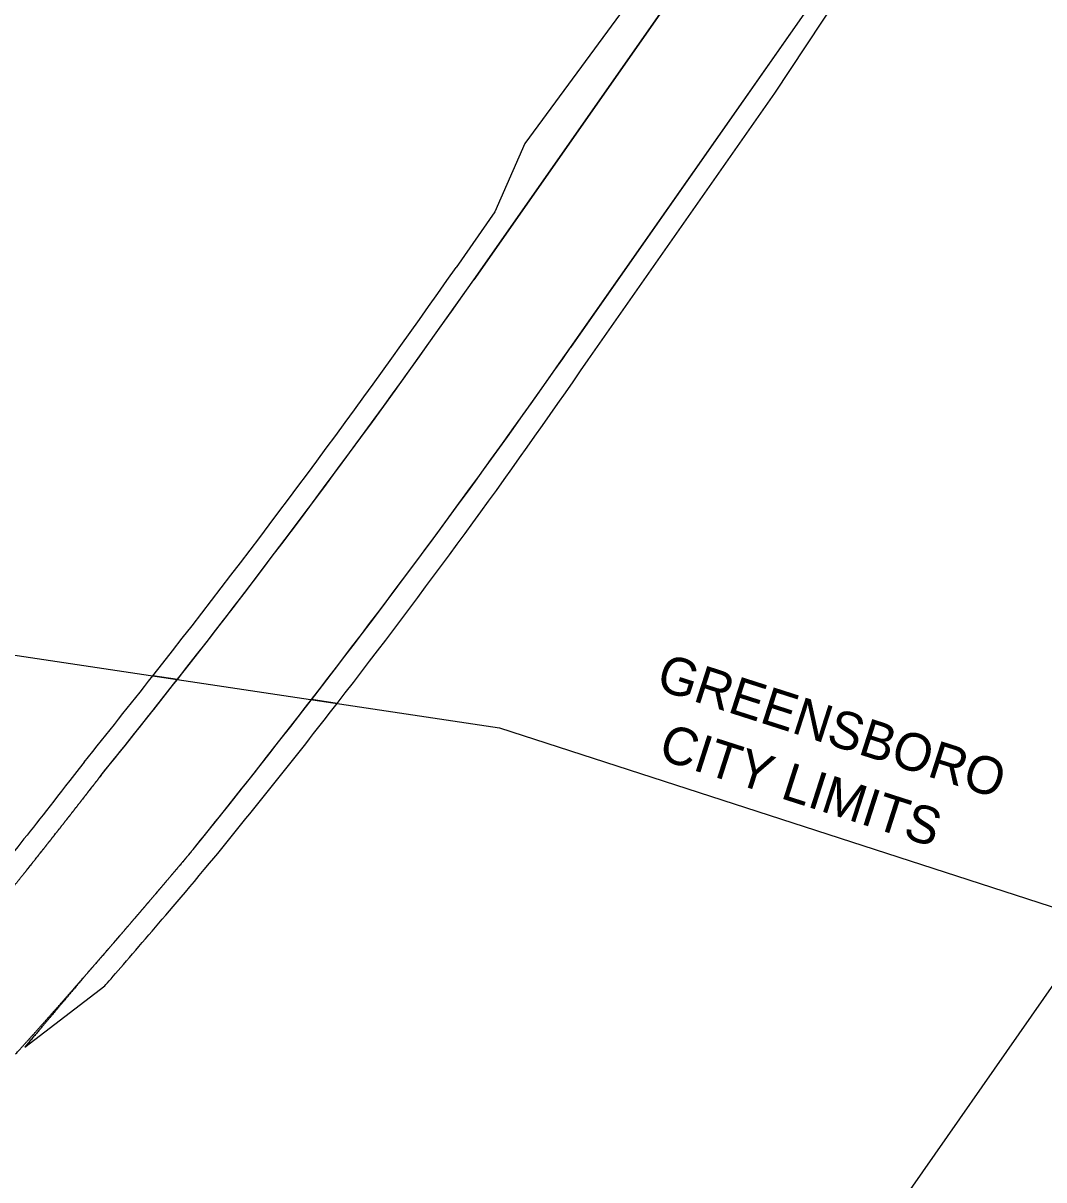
# Model space of a CAD drawing. Extents: x 1731327 to 1735374, y 884856 to 889832.
# Drawn here: x 1732032.5 to 1732222.4, y 885272.3 to 885487.7 of the extents above; entities that cross this region are included whole.
import ezdxf

# ---------------------------------------------------------------- set-up
doc = ezdxf.new("R2010")
doc.units = 0
for name, color, linetype in [('Exist Horizontal Baseline Alignment', 7, 'Continuous'), ('Exist Other Culture Area Outline', 7, 'Continuous'), ('Exist Other Culture Sign Text', 7, 'Continuous'), ('Exist Structure Minor Pipes RCP 24 Inch', 7, 'Continuous')]:
    doc.layers.add(name, color=color, linetype=linetype)

msp = doc.modelspace()

# ---------------------------------------------------------------- linework, layer by layer
at = {"layer": 'Exist Other Culture Area Outline'}
msp.add_lwpolyline([(1732238.91, 886072.74), (1731769.46, 885400.02), (1732118.14, 885156.7), (1732587.59, 885829.41)], close=True, dxfattribs=at)
at = {"layer": 'Exist Other Culture Sign Text'}
msp.add_lwpolyline([(1731775.28, 885408.36), (1732121.12, 885356.5), (1732232.4, 885320.42)], dxfattribs=at)
at = {"layer": 'Exist Structure Minor Pipes RCP 24 Inch'}
for p, q in [((1732169.62, 885516.04), (1732116.34, 885439.87)), ((1732116.34, 885439.87), (1732169.62, 885516.04)), ((1732134.37, 885427.26), (1732191.03, 885508.26)), ((1732190.43, 885507.41), (1732134.37, 885427.26)), ((1732172.39, 885474.63), (1732193.35, 885506.34)), ((1732137.65, 885424.97), (1732172.39, 885474.63)), ((1732125.88, 885465.23), (1732120.29, 885452.5)), ((1732120.29, 885452.5), (1732113.06, 885442.17)), ((1732061.21, 885365.48), (1732056.66, 885366.17)), ((1732056.66, 885366.17), (1732061.21, 885365.48)), ((1732086.17, 885361.74), (1732090.93, 885361.03)), ((1732090.93, 885361.03), (1732086.17, 885361.74)), ((1732032.82, 885297.07), (1732047.69, 885308.44))]:
    msp.add_line(p, q, dxfattribs=at)
msp.add_lwpolyline([(1732160.1, 885512.01), (1732152.44, 885501.5), (1732125.88, 885465.23)], dxfattribs=at)
for centre, radius, start, end in [((1730732.36, 886408.03), 1685, 321.80683, 325.02552), ((1730732.37, 886408.04), 1689, 321.1108, 325.02513), ((1730732.37, 886408.04), 1689, 321.88369, 325.02513), ((1730732.37, 886408.04), 1711, 321.1108, 325.02513), ((1730732.37, 886408.04), 1711, 322.30115, 325.02513), ((1730992.09, 886212.81), 1390.32, 322.21856, 325.48235), ((1730732.36, 886408.03), 1685, 321.10848, 321.80683), ((1730732.37, 886408.04), 1689, 321.1108, 321.88369), ((1730732.37, 886408.04), 1711, 321.1108, 322.30115), ((1730992.09, 886212.81), 1390.32, 320.65011, 322.21856)]:
    msp.add_arc(centre, radius, start, end, dxfattribs=at)
for points, degree in [([(1732043.86, 885350.1), (1732038.81, 885343.58), (1732032.68, 885335.78), (1732026.49, 885328.04), (1732025.45, 885326.74)], 3), ([(1732047.02, 885347.65), (1732046.89, 885347.48), (1732046.75, 885347.3), (1732046.61, 885347.12), (1732046.47, 885346.95), (1732046.34, 885346.77), (1732046.2, 885346.59), (1732046.06, 885346.42), (1732045.93, 885346.24), (1732045.79, 885346.06), (1732045.65, 885345.89), (1732045.51, 885345.71), (1732045.38, 885345.53), (1732045.24, 885345.35), (1732045.1, 885345.18), (1732044.97, 885345), (1732044.83, 885344.82), (1732044.69, 885344.65), (1732044.55, 885344.47), (1732044.42, 885344.29), (1732044.28, 885344.12), (1732044.14, 885343.94), (1732044, 885343.76), (1732043.87, 885343.59), (1732043.73, 885343.41), (1732043.59, 885343.23), (1732043.45, 885343.06), (1732043.32, 885342.88), (1732043.18, 885342.71), (1732043.04, 885342.53), (1732042.9, 885342.35), (1732042.76, 885342.18), (1732042.63, 885342), (1732042.49, 885341.82), (1732042.35, 885341.65), (1732042.21, 885341.47), (1732042.08, 885341.29), (1732041.94, 885341.12), (1732041.8, 885340.94), (1732041.66, 885340.76), (1732041.52, 885340.59), (1732041.39, 885340.41), (1732041.25, 885340.24), (1732041.11, 885340.06), (1732040.97, 885339.88), (1732040.83, 885339.71), (1732040.7, 885339.53), (1732040.56, 885339.35), (1732040.42, 885339.18), (1732040.28, 885339), (1732040.14, 885338.83), (1732040.01, 885338.65), (1732039.87, 885338.47), (1732039.73, 885338.3), (1732039.59, 885338.12), (1732039.45, 885337.95), (1732039.31, 885337.77), (1732039.18, 885337.59), (1732039.04, 885337.42), (1732038.9, 885337.24), (1732038.76, 885337.07), (1732038.62, 885336.89), (1732038.48, 885336.71), (1732038.35, 885336.54), (1732038.21, 885336.36), (1732038.07, 885336.19), (1732037.93, 885336.01), (1732037.79, 885335.84), (1732037.65, 885335.66), (1732037.51, 885335.48), (1732037.38, 885335.31), (1732037.24, 885335.13), (1732037.1, 885334.96), (1732037.01, 885334.85), (1732036.92, 885334.74), (1732036.84, 885334.63)], 3), ([(1732045.02, 885345.07), (1732045.14, 885345.23), (1732045.26, 885345.38), (1732045.38, 885345.53), (1732045.51, 885345.71), (1732045.65, 885345.89), (1732045.79, 885346.06), (1732045.93, 885346.24), (1732046.06, 885346.42), (1732046.2, 885346.59), (1732046.34, 885346.77), (1732046.47, 885346.95), (1732046.61, 885347.12), (1732046.75, 885347.3), (1732046.89, 885347.48), (1732047.02, 885347.65)], 3), ([(1732043.51, 885343.14), (1732043.58, 885343.23), (1732043.66, 885343.32), (1732043.73, 885343.41), (1732043.87, 885343.59), (1732044, 885343.76), (1732044.14, 885343.94), (1732044.28, 885344.12), (1732044.42, 885344.29), (1732044.55, 885344.47), (1732044.55, 885344.47), (1732044.55, 885344.47), (1732044.55, 885344.47)], 3), ([(1732044.55, 885344.47), (1732044.69, 885344.65), (1732044.83, 885344.82), (1732044.97, 885345), (1732044.98, 885345.02), (1732045, 885345.05), (1732045.02, 885345.07)], 3), ([(1732044.55, 885344.47), (1732044.55, 885344.47), (1732044.55, 885344.47), (1732044.55, 885344.47)], 2), ([(1732041.66, 885340.76), (1732041.66, 885340.76), (1732041.66, 885340.76), (1732041.66, 885340.76), (1732041.8, 885340.94), (1732041.94, 885341.12), (1732042.08, 885341.29), (1732042.21, 885341.47), (1732042.35, 885341.65), (1732042.49, 885341.82), (1732042.56, 885341.91), (1732042.62, 885342), (1732042.69, 885342.08)], 3), ([(1732042.69, 885342.08), (1732042.76, 885342.17), (1732042.83, 885342.26), (1732042.9, 885342.35), (1732042.95, 885342.41), (1732042.99, 885342.46), (1732043.03, 885342.52)], 3), ([(1732043.03, 885342.52), (1732043.13, 885342.64), (1732043.22, 885342.76), (1732043.32, 885342.88), (1732043.38, 885342.97), (1732043.45, 885343.05), (1732043.51, 885343.14)], 3), ([(1732038.43, 885336.65), (1732038.54, 885336.79), (1732038.65, 885336.93), (1732038.76, 885337.07), (1732038.9, 885337.24), (1732039.04, 885337.42), (1732039.18, 885337.59), (1732039.31, 885337.77), (1732039.45, 885337.95), (1732039.59, 885338.12), (1732039.73, 885338.3), (1732039.87, 885338.47), (1732040.01, 885338.65), (1732040.14, 885338.83), (1732040.28, 885339), (1732040.42, 885339.18), (1732040.47, 885339.24), (1732040.51, 885339.29), (1732040.56, 885339.35)], 3), ([(1732040.56, 885339.35), (1732040.65, 885339.47), (1732040.74, 885339.59), (1732040.83, 885339.71), (1732040.97, 885339.88), (1732041.11, 885340.06), (1732041.25, 885340.24), (1732041.39, 885340.41), (1732041.52, 885340.59), (1732041.66, 885340.76)], 3), ([(1732036.84, 885334.63), (1732036.92, 885334.74), (1732037.01, 885334.85), (1732037.1, 885334.96), (1732037.24, 885335.13), (1732037.38, 885335.31), (1732037.51, 885335.48), (1732037.65, 885335.66), (1732037.79, 885335.84), (1732037.93, 885336.01), (1732038.07, 885336.19), (1732038.21, 885336.36), (1732038.35, 885336.54), (1732038.37, 885336.57), (1732038.4, 885336.61), (1732038.43, 885336.65)], 3), ([(1732036.84, 885334.63), (1732036.79, 885334.56), (1732036.73, 885334.49), (1732036.68, 885334.43), (1732036.54, 885334.25), (1732036.4, 885334.08), (1732036.27, 885333.9), (1732036.13, 885333.73), (1732035.99, 885333.55), (1732035.85, 885333.38), (1732035.71, 885333.2), (1732035.57, 885333.02), (1732035.43, 885332.85), (1732035.29, 885332.67), (1732035.15, 885332.5), (1732035.02, 885332.32), (1732034.88, 885332.15), (1732034.74, 885331.97), (1732034.6, 885331.8), (1732034.46, 885331.62), (1732034.32, 885331.45), (1732034.18, 885331.27), (1732034.04, 885331.09), (1732033.9, 885330.92), (1732033.76, 885330.74), (1732033.62, 885330.57), (1732033.48, 885330.39), (1732033.35, 885330.22), (1732033.21, 885330.04), (1732033.07, 885329.87), (1732032.93, 885329.69), (1732032.79, 885329.52), (1732032.65, 885329.34), (1732032.51, 885329.17), (1732032.37, 885328.99), (1732032.23, 885328.82), (1732032.09, 885328.64), (1732031.95, 885328.47), (1732031.81, 885328.29), (1732031.67, 885328.12), (1732031.53, 885327.94), (1732031.39, 885327.77), (1732031.25, 885327.59), (1732031.11, 885327.42), (1732030.97, 885327.24), (1732030.83, 885327.07), (1732030.69, 885326.89), (1732030.55, 885326.72), (1732030.41, 885326.54), (1732030.27, 885326.37), (1732030.13, 885326.19), (1732029.99, 885326.02), (1732029.85, 885325.84), (1732029.71, 885325.67), (1732029.57, 885325.49), (1732029.43, 885325.32), (1732029.29, 885325.14), (1732029.15, 885324.97), (1732029.01, 885324.79), (1732028.87, 885324.62), (1732028.73, 885324.45), (1732028.59, 885324.27), (1732028.45, 885324.1), (1732028.31, 885323.92), (1732028.17, 885323.75), (1732028.03, 885323.57), (1732027.89, 885323.4), (1732027.75, 885323.22), (1732027.61, 885323.05), (1732027.47, 885322.87), (1732027.33, 885322.7), (1732027.19, 885322.53), (1732027.05, 885322.35), (1732026.91, 885322.18), (1732026.77, 885322), (1732026.63, 885321.83), (1732026.6, 885321.78), (1732026.56, 885321.74), (1732026.53, 885321.7)], 3), ([(1732035.12, 885332.45), (1732035.22, 885332.58), (1732035.33, 885332.72), (1732035.43, 885332.85), (1732035.57, 885333.02), (1732035.71, 885333.2), (1732035.85, 885333.38)], 3), ([(1732035.85, 885333.38), (1732035.85, 885333.38), (1732035.85, 885333.38), (1732035.85, 885333.38), (1732035.99, 885333.55), (1732036.13, 885333.73), (1732036.27, 885333.9), (1732036.4, 885334.08), (1732036.54, 885334.25), (1732036.68, 885334.43), (1732036.73, 885334.49), (1732036.79, 885334.56), (1732036.84, 885334.63)], 3), ([(1732053.28, 885321.03), (1732053.38, 885321.15), (1732053.48, 885321.27), (1732053.59, 885321.39), (1732053.74, 885321.57), (1732053.88, 885321.74), (1732054.03, 885321.91), (1732054.18, 885322.08), (1732054.33, 885322.25), (1732054.47, 885322.43), (1732054.62, 885322.6), (1732054.77, 885322.77), (1732054.91, 885322.94), (1732055.06, 885323.12), (1732055.21, 885323.29), (1732055.36, 885323.46), (1732055.5, 885323.63), (1732055.65, 885323.81), (1732055.8, 885323.98), (1732055.95, 885324.15), (1732056.09, 885324.32), (1732056.24, 885324.5), (1732056.39, 885324.67), (1732056.53, 885324.84), (1732056.68, 885325.01), (1732056.83, 885325.19), (1732056.97, 885325.36), (1732057.12, 885325.53), (1732057.27, 885325.7), (1732057.41, 885325.88), (1732057.56, 885326.05), (1732057.71, 885326.22), (1732057.86, 885326.4), (1732058, 885326.57), (1732058.15, 885326.74), (1732058.3, 885326.91), (1732058.44, 885327.09), (1732058.59, 885327.26), (1732058.74, 885327.43), (1732058.88, 885327.61), (1732059.03, 885327.78), (1732059.18, 885327.95), (1732059.32, 885328.12), (1732059.47, 885328.3), (1732059.62, 885328.47), (1732059.76, 885328.64), (1732059.91, 885328.82), (1732060.05, 885328.99), (1732060.2, 885329.16), (1732060.35, 885329.34), (1732060.49, 885329.51), (1732060.64, 885329.68), (1732060.79, 885329.85), (1732060.93, 885330.03), (1732061.08, 885330.2), (1732061.23, 885330.37), (1732061.37, 885330.55), (1732061.52, 885330.72), (1732061.66, 885330.89), (1732061.81, 885331.07), (1732061.96, 885331.24), (1732062.1, 885331.41), (1732062.25, 885331.59), (1732062.39, 885331.76), (1732062.54, 885331.93), (1732062.69, 885332.11), (1732062.83, 885332.28), (1732062.98, 885332.45), (1732063.13, 885332.63), (1732063.27, 885332.8), (1732063.42, 885332.97), (1732063.56, 885333.15), (1732063.71, 885333.32), (1732063.85, 885333.5), (1732064, 885333.67), (1732064.15, 885333.84)], 3), ([(1732063.29, 885332.82), (1732063.28, 885332.82), (1732063.28, 885332.81), (1732063.27, 885332.8), (1732063.13, 885332.63), (1732062.98, 885332.45), (1732062.83, 885332.28), (1732062.83, 885332.28), (1732062.83, 885332.28), (1732062.83, 885332.28)], 3), ([(1732063.43, 885332.99), (1732063.38, 885332.93), (1732063.34, 885332.88), (1732063.29, 885332.82)], 2), ([(1732063.68, 885333.29), (1732063.6, 885333.19), (1732063.51, 885333.09), (1732063.43, 885332.99)], 2), ([(1732064.15, 885333.84), (1732064, 885333.67), (1732063.85, 885333.5), (1732063.71, 885333.32), (1732063.7, 885333.31), (1732063.69, 885333.3), (1732063.68, 885333.29)], 3), ([(1732032.51, 885329.17), (1732032.65, 885329.34), (1732032.79, 885329.52), (1732032.93, 885329.69), (1732033.07, 885329.87), (1732033.21, 885330.04), (1732033.35, 885330.22), (1732033.48, 885330.39), (1732033.62, 885330.57), (1732033.76, 885330.74)], 3), ([(1732033.76, 885330.74), (1732033.79, 885330.77), (1732033.81, 885330.81), (1732033.84, 885330.84)], 2), ([(1732033.76, 885330.74), (1732033.76, 885330.74), (1732033.76, 885330.74), (1732033.76, 885330.74), (1732033.76, 885330.74), (1732033.76, 885330.74), (1732033.76, 885330.74)], 3), ([(1732033.76, 885330.74), (1732033.76, 885330.74), (1732033.76, 885330.74), (1732033.76, 885330.74)], 2), ([(1732033.84, 885330.84), (1732033.95, 885330.98), (1732034.07, 885331.13), (1732034.18, 885331.27), (1732034.32, 885331.45), (1732034.46, 885331.62), (1732034.6, 885331.8), (1732034.71, 885331.94), (1732034.83, 885332.09), (1732034.95, 885332.24)], 3), ([(1732034.95, 885332.24), (1732034.97, 885332.26), (1732034.99, 885332.29), (1732035.02, 885332.32), (1732035.05, 885332.37), (1732035.08, 885332.41), (1732035.12, 885332.45)], 3), ([(1732047.69, 885308.44), (1732048.74, 885309.64), (1732055.3, 885317.2), (1732061.79, 885324.82), (1732067.21, 885331.27)], 3), ([(1732061.82, 885331.08), (1732061.72, 885330.96), (1732061.62, 885330.84), (1732061.52, 885330.72), (1732061.37, 885330.55), (1732061.23, 885330.37), (1732061.08, 885330.2), (1732060.93, 885330.03), (1732060.79, 885329.85), (1732060.64, 885329.68), (1732060.49, 885329.51), (1732060.35, 885329.34), (1732060.2, 885329.16), (1732060.05, 885328.99), (1732059.91, 885328.82), (1732059.76, 885328.64), (1732059.62, 885328.47), (1732059.47, 885328.3), (1732059.32, 885328.12), (1732059.32, 885328.12), (1732059.32, 885328.12), (1732059.32, 885328.12)], 3), ([(1732062.39, 885331.76), (1732062.25, 885331.59), (1732062.1, 885331.41), (1732061.96, 885331.24), (1732061.91, 885331.19), (1732061.87, 885331.13), (1732061.82, 885331.08)], 3), ([(1732062.83, 885332.28), (1732062.69, 885332.11), (1732062.54, 885331.93), (1732062.39, 885331.76)], 2), ([(1732062.83, 885332.28), (1732062.83, 885332.28), (1732062.83, 885332.28), (1732062.83, 885332.28)], 2), ([(1732058.44, 885327.09), (1732058.3, 885326.91), (1732058.15, 885326.74), (1732058, 885326.57), (1732057.86, 885326.4), (1732057.71, 885326.22), (1732057.56, 885326.05), (1732057.41, 885325.88), (1732057.27, 885325.7), (1732057.12, 885325.53)], 3), ([(1732059.32, 885328.12), (1732059.17, 885327.95), (1732059.03, 885327.78), (1732058.88, 885327.61), (1732058.74, 885327.43), (1732058.59, 885327.26), (1732058.44, 885327.09), (1732058.44, 885327.09), (1732058.44, 885327.09), (1732058.44, 885327.09)], 3), ([(1732057.12, 885325.53), (1732056.97, 885325.36), (1732056.83, 885325.19), (1732056.68, 885325.01), (1732056.53, 885324.84), (1732056.39, 885324.67), (1732056.24, 885324.5), (1732056.09, 885324.32), (1732055.95, 885324.15), (1732055.8, 885323.98), (1732055.72, 885323.88), (1732055.63, 885323.79), (1732055.55, 885323.69)], 3), ([(1732057.12, 885325.53), (1732057.12, 885325.53), (1732057.12, 885325.53), (1732057.12, 885325.53)], 2), ([(1732057.12, 885325.53), (1732057.12, 885325.53), (1732057.12, 885325.53), (1732057.12, 885325.53), (1732057.12, 885325.53), (1732057.12, 885325.53), (1732057.12, 885325.53)], 3), ([(1732055.55, 885323.69), (1732055.49, 885323.61), (1732055.42, 885323.54), (1732055.36, 885323.46), (1732055.21, 885323.29), (1732055.06, 885323.12), (1732054.91, 885322.94), (1732054.77, 885322.77), (1732054.62, 885322.6), (1732054.47, 885322.43), (1732054.33, 885322.25), (1732054.18, 885322.08), (1732054.03, 885321.91), (1732053.88, 885321.74), (1732053.74, 885321.57), (1732053.59, 885321.39), (1732053.59, 885321.39), (1732053.59, 885321.39), (1732053.59, 885321.39)], 3), ([(1732042.28, 885308.32), (1732042.34, 885308.39), (1732042.41, 885308.47), (1732042.47, 885308.54), (1732042.62, 885308.71), (1732042.77, 885308.88), (1732042.91, 885309.05), (1732043.06, 885309.22), (1732043.21, 885309.39), (1732043.36, 885309.56), (1732043.51, 885309.73), (1732043.66, 885309.9), (1732043.81, 885310.07), (1732043.96, 885310.24), (1732044.11, 885310.42), (1732044.26, 885310.59), (1732044.4, 885310.76), (1732044.55, 885310.93), (1732044.7, 885311.1), (1732044.85, 885311.27), (1732045, 885311.44), (1732045.15, 885311.61), (1732045.3, 885311.78), (1732045.45, 885311.95), (1732045.59, 885312.13), (1732045.74, 885312.3), (1732045.89, 885312.47), (1732046.04, 885312.64), (1732046.19, 885312.81), (1732046.34, 885312.98), (1732046.49, 885313.15), (1732046.63, 885313.32), (1732046.78, 885313.49), (1732046.93, 885313.67), (1732047.08, 885313.84), (1732047.23, 885314.01), (1732047.38, 885314.18), (1732047.52, 885314.35), (1732047.67, 885314.52), (1732047.82, 885314.69), (1732047.97, 885314.87), (1732048.12, 885315.04), (1732048.27, 885315.21), (1732048.41, 885315.38), (1732048.56, 885315.55), (1732048.71, 885315.72), (1732048.86, 885315.89), (1732049.01, 885316.07), (1732049.16, 885316.24), (1732049.3, 885316.41), (1732049.45, 885316.58), (1732049.6, 885316.75), (1732049.75, 885316.92), (1732049.9, 885317.1), (1732050.04, 885317.27), (1732050.19, 885317.44), (1732050.34, 885317.61), (1732050.49, 885317.78), (1732050.64, 885317.95), (1732050.78, 885318.13), (1732050.93, 885318.3), (1732051.08, 885318.47), (1732051.23, 885318.64), (1732051.37, 885318.81), (1732051.52, 885318.99), (1732051.67, 885319.16), (1732051.82, 885319.33), (1732051.97, 885319.5), (1732052.11, 885319.67), (1732052.26, 885319.84), (1732052.41, 885320.02), (1732052.56, 885320.19), (1732052.7, 885320.36), (1732052.85, 885320.53), (1732053, 885320.71), (1732053.15, 885320.88), (1732053.19, 885320.93), (1732053.23, 885320.98), (1732053.28, 885321.03)], 3), ([(1732052.7, 885320.36), (1732052.7, 885320.36), (1732052.7, 885320.36), (1732052.7, 885320.36), (1732052.56, 885320.19), (1732052.41, 885320.02), (1732052.26, 885319.84), (1732052.11, 885319.67), (1732051.97, 885319.5), (1732051.82, 885319.33), (1732051.67, 885319.16), (1732051.52, 885318.99), (1732051.37, 885318.81), (1732051.23, 885318.64), (1732051.08, 885318.47), (1732050.93, 885318.3)], 3), ([(1732053.15, 885320.88), (1732053.15, 885320.88), (1732053.15, 885320.88), (1732053.15, 885320.88), (1732053, 885320.71), (1732052.85, 885320.53), (1732052.7, 885320.36)], 3), ([(1732053.28, 885321.03), (1732053.23, 885320.98), (1732053.19, 885320.93), (1732053.15, 885320.88)], 2), ([(1732053.59, 885321.39), (1732053.48, 885321.27), (1732053.38, 885321.15), (1732053.28, 885321.03)], 2), ([(1732050.49, 885317.78), (1732050.34, 885317.61), (1732050.19, 885317.44), (1732050.04, 885317.27)], 2), ([(1732050.93, 885318.3), (1732050.93, 885318.3), (1732050.93, 885318.3), (1732050.93, 885318.3), (1732050.78, 885318.13), (1732050.64, 885317.95), (1732050.49, 885317.78), (1732050.49, 885317.78), (1732050.49, 885317.78), (1732050.49, 885317.78)], 3), ([(1732049.6, 885316.75), (1732049.45, 885316.58), (1732049.3, 885316.41), (1732049.16, 885316.24), (1732049.01, 885316.07), (1732048.86, 885315.89), (1732048.71, 885315.72), (1732048.57, 885315.55), (1732048.42, 885315.39), (1732048.27, 885315.22)], 3), ([(1732050.04, 885317.27), (1732049.9, 885317.1), (1732049.75, 885316.92), (1732049.6, 885316.75)], 2), ([(1732049.6, 885316.75), (1732049.6, 885316.75), (1732049.6, 885316.75), (1732049.6, 885316.75), (1732049.6, 885316.75), (1732049.6, 885316.75), (1732049.6, 885316.75)], 3), ([(1732050.04, 885317.27), (1732050.04, 885317.27), (1732050.04, 885317.27), (1732050.04, 885317.27)], 2), ([(1732047.38, 885314.18), (1732047.23, 885314.01), (1732047.08, 885313.84), (1732046.93, 885313.67), (1732046.78, 885313.49), (1732046.63, 885313.32), (1732046.49, 885313.15), (1732046.34, 885312.98), (1732046.19, 885312.81), (1732046.04, 885312.64)], 3), ([(1732048.18, 885315.1), (1732048.06, 885314.97), (1732047.94, 885314.83), (1732047.82, 885314.69), (1732047.67, 885314.52), (1732047.52, 885314.35), (1732047.38, 885314.18)], 3), ([(1732048.27, 885315.22), (1732048.27, 885315.21), (1732048.27, 885315.21), (1732048.27, 885315.21), (1732048.24, 885315.17), (1732048.21, 885315.14), (1732048.18, 885315.1)], 3), ([(1732044.7, 885311.1), (1732044.7, 885311.1), (1732044.7, 885311.1), (1732044.7, 885311.1), (1732044.55, 885310.93), (1732044.4, 885310.76), (1732044.26, 885310.59), (1732044.11, 885310.42), (1732043.96, 885310.24), (1732043.81, 885310.07), (1732043.76, 885310.02), (1732043.71, 885309.96), (1732043.66, 885309.91)], 3), ([(1732045.31, 885311.79), (1732045.25, 885311.73), (1732045.2, 885311.67), (1732045.15, 885311.61), (1732045, 885311.44), (1732044.85, 885311.27), (1732044.7, 885311.1)], 3), ([(1732046.04, 885312.64), (1732046.04, 885312.64), (1732046.04, 885312.64), (1732046.04, 885312.64), (1732045.89, 885312.47), (1732045.74, 885312.3), (1732045.59, 885312.13), (1732045.5, 885312.01), (1732045.4, 885311.9), (1732045.31, 885311.79)], 3), ([(1732046.04, 885312.64), (1732046.04, 885312.64), (1732046.04, 885312.64), (1732046.04, 885312.64)], 2), ([(1732043.66, 885309.91), (1732040.06, 885305.61), (1732036.46, 885301.33), (1732032.82, 885297.07)], 2), ([(1732031.11, 885295.77), (1732031.42, 885296.11), (1732031.73, 885296.44), (1732032.03, 885296.78), (1732032.19, 885296.95), (1732032.34, 885297.12), (1732032.49, 885297.29), (1732032.64, 885297.46), (1732032.8, 885297.63), (1732032.95, 885297.8), (1732033.1, 885297.97), (1732033.25, 885298.14), (1732033.41, 885298.31), (1732033.56, 885298.47), (1732033.71, 885298.64), (1732033.86, 885298.81), (1732034.02, 885298.98), (1732034.17, 885299.15), (1732034.32, 885299.32), (1732034.47, 885299.49), (1732034.63, 885299.66), (1732034.78, 885299.83), (1732034.93, 885300), (1732035.08, 885300.17), (1732035.23, 885300.34), (1732035.39, 885300.51), (1732035.54, 885300.68), (1732035.69, 885300.85), (1732035.84, 885301.02), (1732035.99, 885301.19), (1732036.14, 885301.36), (1732036.3, 885301.53), (1732036.45, 885301.7), (1732036.6, 885301.87), (1732036.75, 885302.04), (1732036.9, 885302.21), (1732037.05, 885302.38), (1732037.21, 885302.56), (1732037.36, 885302.73), (1732037.51, 885302.9), (1732037.66, 885303.07), (1732037.81, 885303.24), (1732037.96, 885303.41), (1732038.11, 885303.58), (1732038.26, 885303.75), (1732038.41, 885303.92), (1732038.57, 885304.09), (1732038.72, 885304.26), (1732038.87, 885304.43), (1732039.02, 885304.6), (1732039.17, 885304.78), (1732039.32, 885304.95), (1732039.47, 885305.12), (1732039.62, 885305.29), (1732039.77, 885305.46), (1732039.92, 885305.63), (1732040.07, 885305.8), (1732040.22, 885305.97), (1732040.37, 885306.15), (1732040.52, 885306.32), (1732040.68, 885306.49), (1732040.83, 885306.66), (1732040.97, 885306.83), (1732041.12, 885307), (1732041.27, 885307.17), (1732041.42, 885307.34), (1732041.57, 885307.51), (1732041.72, 885307.68), (1732041.87, 885307.85), (1732042.02, 885308.02), (1732042.11, 885308.12), (1732042.19, 885308.22), (1732042.28, 885308.32)], 3)]:
    msp.add_open_spline(points, degree=degree, dxfattribs=at)

# ---------------------------------------------------------------- texts
at = {"layer": 'Exist Horizontal Baseline Alignment'}
for s, p in [('GREENSBORO', (1732150, 885363.78)), ('CITY LIMITS', (1732150.43, 885350.78))]:
    msp.add_text(s, height=7, rotation=342.1792, dxfattribs=at).set_placement(p)

doc.saveas('drawing.dxf')
